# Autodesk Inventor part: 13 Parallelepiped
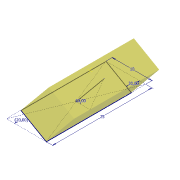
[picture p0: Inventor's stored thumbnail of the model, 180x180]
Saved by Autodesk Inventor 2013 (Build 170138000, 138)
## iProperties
Created: 2012-10
Part Number: 13 Parallelepiped
Material: Allgemein
Vendor: www.inventor-faq.de
Document SubType Name: Modeling
Designer: Administrator
Manufacturer: www.inventor-faq.de
Density: 1 g/cm^3
RuleStatus: InUse
AfterDocOpen0: inventorfaq
BeforeDocSave0: inventorfaq
Author: Administrator
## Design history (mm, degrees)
sketch "Skizze1"
  geometry: L1 (-5, -12.5)-(5, -12.5); L2 (5, -12.5)-(5, 12.5); L3 (5, 12.5)-(-5, 12.5); L4 (-5, 12.5)-(-5, -12.5); L5 (-5, -12.5)-(5, 12.5); L6 (5, -12.5)-(-5, 12.5); L7 (-5, 12.5)-(5, 8.86); L8 (5, 8.86)-(5, -12.5); L9 (5, -12.5)-(-5, -8.86); L10 (-5, -8.86)-(-5, 12.5); 1 further point
  constraints: 20 end point, 5 parallel, 2 midpoint, 2 point on line, 1 horizontal, 1 perpendicular
  dimensions: "d0" = 10 distance of L3.end L2.end; "d1" = 25 distance of L2.end L1.end; "d5" = 20 deg angle of L3 L7; "d6" = 20 deg angle of L1 L9 (derived)
sketch "Skizze2"
  geometry: L1 (0, 0)-(3.501, 5); L2 (0, 0)-(6.104, 0)
  constraints: 4 end point, 1 equal length, 1 horizontal
  dimensions: "d3" = 55 deg angle of L2 L1; "d11" = 5 vertical distance of L1.end L1.start
workplane "Arbeitsebene1"
sketch "Skizze3"
  geometry: L1 (0, 0)-(6.104, 3.524); L2 (6.104, 3.524)-(0, 3.524); L3 (0, 3.524)-(0, 0); 1 further point
  constraints: 6 end point, 1 horizontal, 1 perpendicular, 1 vertical alignment
  dimensions: "d9" = 60 deg angle of L3 L1
feature "Sweeping2" sketch "Skizze3" dims "d12" = 0
node "Volumenkörper2"
other parameters: "d8" = 90 deg
